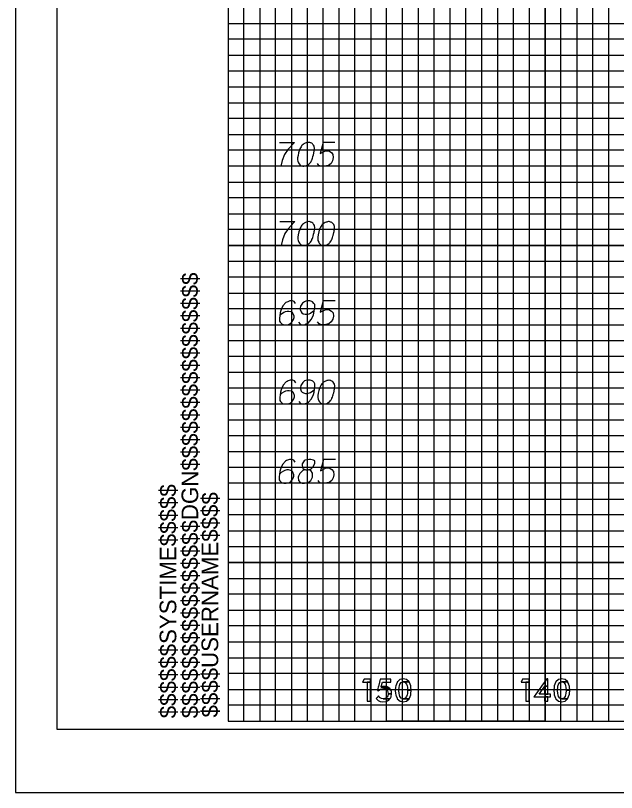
# Model space of a CAD drawing. Extents: x -13 to 323, y -5 to 1431.
# Drawn here: x -13.4 to 24.5, y -4.5 to 44.5 of the extents above; entities that cross this region are included whole.
import ezdxf

# ---------------------------------------------------------------- set-up
doc = ezdxf.new("R2010")
doc.units = 0
for name, color, linetype in [('Prop XS Elevation Labels', 7, 'Continuous'), ('Prop XS Offset Labels', 7, 'Continuous'), ('Scratch_Level_3', 7, 'Continuous'), ('Sheet Cross Section CELL', 7, 'Continuous'), ('Sheet Cross Section Grid Major CELL', 7, 'Continuous'), ('Sheet Cross Section Grid Middle CELL', 7, 'Continuous'), ('Sheet Cross Section Grid Minor 1 CELL', 7, 'Continuous'), ('Sheet Cross Section Grid Minor 2 CELL', 7, 'Continuous'), ('Sheet Cutting Line CELL', 7, 'Continuous'), ('Sheet DOT Grid CELL', 7, 'Continuous'), ('Sheet Plot Border Inside CELL', 7, 'Continuous'), ('Sheet Plot Border Outside CELL', 7, 'Continuous')]:
    doc.layers.add(name, color=color, linetype=linetype)

msp = doc.modelspace()

# ---------------------------------------------------------------- linework, layer by layer
at = {"layer": 'Prop XS Elevation Labels'}
for points in [[(3.258, 36.5), (4.203, 36.5), (4.144, 36.441), (3.801, 36.075), (3.565, 35.744), (3.423, 35.354), (3.329, 35)], [(5.1, 36.5), (5.077, 36.5), (5.006, 36.488), (4.959, 36.476), (4.923, 36.465), (4.864, 36.441), (4.793, 36.406), (4.734, 36.37), (4.675, 36.323), (4.64, 36.276), (4.604, 36.217), (4.569, 36.158), (4.534, 36.087), (4.51, 36.039), (4.486, 35.969), (4.451, 35.85), (4.415, 35.673), (4.392, 35.531), (4.392, 35.402), (4.404, 35.307), (4.451, 35.201), (4.486, 35.142), (4.545, 35.071), (4.616, 35.024), (4.652, 35.012), (4.723, 35), (4.781, 35), (4.876, 35.012), (4.959, 35.035), (5.018, 35.071), (5.1, 35.13), (5.136, 35.165), (5.183, 35.213), (5.219, 35.26), (5.242, 35.295), (5.266, 35.354), (5.278, 35.378), (5.301, 35.437), (5.325, 35.508), (5.349, 35.579), (5.36, 35.626), (5.372, 35.661), (5.384, 35.709), (5.408, 35.815), (5.419, 35.874), (5.431, 35.933), (5.443, 36.016), (5.455, 36.122), (5.455, 36.158), (5.443, 36.205), (5.431, 36.252), (5.396, 36.323), (5.36, 36.37), (5.325, 36.406), (5.278, 36.441), (5.23, 36.465), (5.195, 36.476), (5.16, 36.488), (5.1, 36.5)], [(6.742, 36.5), (5.998, 36.5), (5.809, 35.791), (6.152, 35.969), (6.352, 35.969), (6.518, 35.862), (6.612, 35.744), (6.636, 35.543), (6.6, 35.342), (6.506, 35.177), (6.341, 35.047), (6.057, 35), (5.845, 35), (5.738, 35.047), (5.644, 35.177)], [(3.276, 31.5), (4.22, 31.5), (4.161, 31.441), (3.819, 31.075), (3.583, 30.744), (3.441, 30.354), (3.346, 30)], [(5.118, 31.5), (5.094, 31.5), (5.024, 31.488), (4.977, 31.476), (4.941, 31.465), (4.882, 31.441), (4.811, 31.406), (4.752, 31.37), (4.693, 31.323), (4.658, 31.276), (4.622, 31.217), (4.587, 31.158), (4.551, 31.087), (4.528, 31.039), (4.504, 30.969), (4.469, 30.85), (4.433, 30.673), (4.409, 30.531), (4.409, 30.402), (4.421, 30.307), (4.469, 30.201), (4.504, 30.142), (4.563, 30.071), (4.634, 30.024), (4.669, 30.012), (4.74, 30), (4.799, 30), (4.894, 30.012), (4.977, 30.035), (5.036, 30.071), (5.118, 30.13), (5.154, 30.165), (5.201, 30.213), (5.236, 30.26), (5.26, 30.295), (5.283, 30.354), (5.295, 30.378), (5.319, 30.437), (5.342, 30.508), (5.366, 30.579), (5.378, 30.626), (5.39, 30.661), (5.402, 30.709), (5.425, 30.815), (5.437, 30.874), (5.449, 30.933), (5.461, 31.016), (5.473, 31.122), (5.473, 31.158), (5.461, 31.205), (5.449, 31.252), (5.413, 31.323), (5.378, 31.37), (5.342, 31.406), (5.295, 31.441), (5.248, 31.465), (5.213, 31.476), (5.177, 31.488), (5.118, 31.5)], [(6.37, 31.5), (6.346, 31.5), (6.276, 31.488), (6.228, 31.476), (6.193, 31.465), (6.134, 31.441), (6.063, 31.406), (6.004, 31.37), (5.945, 31.323), (5.909, 31.276), (5.874, 31.217), (5.838, 31.158), (5.803, 31.087), (5.779, 31.039), (5.756, 30.969), (5.721, 30.85), (5.685, 30.673), (5.661, 30.531), (5.661, 30.402), (5.673, 30.307), (5.721, 30.201), (5.756, 30.142), (5.815, 30.071), (5.886, 30.024), (5.921, 30.012), (5.992, 30), (6.051, 30), (6.146, 30.012), (6.228, 30.035), (6.287, 30.071), (6.37, 30.13), (6.406, 30.165), (6.453, 30.213), (6.488, 30.26), (6.512, 30.295), (6.535, 30.354), (6.547, 30.378), (6.571, 30.437), (6.594, 30.508), (6.618, 30.579), (6.63, 30.626), (6.642, 30.661), (6.653, 30.709), (6.677, 30.815), (6.689, 30.874), (6.701, 30.933), (6.713, 31.016), (6.724, 31.122), (6.724, 31.158), (6.713, 31.205), (6.701, 31.252), (6.665, 31.323), (6.63, 31.37), (6.594, 31.406), (6.547, 31.441), (6.5, 31.465), (6.464, 31.476), (6.429, 31.488), (6.37, 31.5)], [(4.262, 26.335), (4.168, 26.465), (4.061, 26.5), (3.896, 26.5), (3.778, 26.453), (3.707, 26.429), (3.648, 26.394), (3.459, 26.181), (3.329, 25.898), (3.294, 25.744), (3.246, 25.402), (3.246, 25.224), (3.294, 25.154), (3.388, 25.059), (3.423, 25.035), (3.542, 25), (3.695, 25), (3.813, 25.024), (3.896, 25.047), (4.014, 25.142), (4.132, 25.331), (4.168, 25.449), (4.168, 25.543), (4.109, 25.697), (4.061, 25.756), (3.979, 25.803), (3.837, 25.839), (3.73, 25.839), (3.601, 25.803), (3.518, 25.768), (3.376, 25.673), (3.305, 25.614), (3.27, 25.579)], [(4.451, 25.165), (4.545, 25.035), (4.652, 25), (4.817, 25), (4.935, 25.047), (5.006, 25.071), (5.065, 25.106), (5.254, 25.319), (5.384, 25.602), (5.419, 25.756), (5.467, 26.098), (5.467, 26.276), (5.419, 26.346), (5.325, 26.441), (5.289, 26.465), (5.171, 26.5), (5.018, 26.5), (4.9, 26.476), (4.817, 26.453), (4.699, 26.358), (4.581, 26.169), (4.545, 26.051), (4.545, 25.957), (4.604, 25.803), (4.652, 25.744), (4.734, 25.697), (4.876, 25.661), (4.982, 25.661), (5.112, 25.697), (5.195, 25.732), (5.337, 25.827), (5.408, 25.886), (5.443, 25.921)], [(6.754, 26.5), (6.01, 26.5), (5.821, 25.791), (6.163, 25.969), (6.364, 25.969), (6.529, 25.862), (6.624, 25.744), (6.647, 25.543), (6.612, 25.342), (6.517, 25.177), (6.352, 25.047), (6.069, 25), (5.856, 25), (5.75, 25.047), (5.655, 25.177)], [(4.28, 21.335), (4.185, 21.465), (4.079, 21.5), (3.914, 21.5), (3.795, 21.453), (3.725, 21.429), (3.666, 21.394), (3.477, 21.181), (3.347, 20.898), (3.311, 20.744), (3.264, 20.402), (3.264, 20.224), (3.311, 20.154), (3.406, 20.059), (3.441, 20.035), (3.559, 20), (3.713, 20), (3.831, 20.024), (3.914, 20.047), (4.032, 20.142), (4.15, 20.331), (4.185, 20.449), (4.185, 20.543), (4.126, 20.697), (4.079, 20.756), (3.996, 20.803), (3.854, 20.839), (3.748, 20.839), (3.618, 20.803), (3.536, 20.768), (3.394, 20.673), (3.323, 20.614), (3.288, 20.579)], [(4.468, 20.165), (4.563, 20.035), (4.669, 20), (4.835, 20), (4.953, 20.047), (5.024, 20.071), (5.083, 20.106), (5.272, 20.319), (5.401, 20.602), (5.437, 20.756), (5.484, 21.098), (5.484, 21.276), (5.437, 21.346), (5.342, 21.441), (5.307, 21.465), (5.189, 21.5), (5.036, 21.5), (4.917, 21.476), (4.835, 21.453), (4.717, 21.358), (4.598, 21.169), (4.563, 21.051), (4.563, 20.957), (4.622, 20.803), (4.669, 20.744), (4.752, 20.697), (4.894, 20.661), (5, 20.661), (5.13, 20.697), (5.213, 20.732), (5.354, 20.827), (5.425, 20.886), (5.461, 20.921)], [(6.382, 21.5), (6.358, 21.5), (6.287, 21.488), (6.24, 21.476), (6.204, 21.465), (6.145, 21.441), (6.074, 21.406), (6.015, 21.37), (5.956, 21.323), (5.921, 21.276), (5.885, 21.217), (5.85, 21.158), (5.815, 21.087), (5.791, 21.039), (5.767, 20.969), (5.732, 20.85), (5.697, 20.673), (5.673, 20.531), (5.673, 20.402), (5.685, 20.307), (5.732, 20.201), (5.767, 20.142), (5.827, 20.071), (5.897, 20.024), (5.933, 20.012), (6.004, 20), (6.063, 20), (6.157, 20.012), (6.24, 20.035), (6.299, 20.071), (6.382, 20.13), (6.417, 20.165), (6.464, 20.213), (6.5, 20.26), (6.523, 20.295), (6.547, 20.354), (6.559, 20.378), (6.582, 20.437), (6.606, 20.508), (6.63, 20.579), (6.642, 20.626), (6.653, 20.661), (6.665, 20.709), (6.689, 20.815), (6.701, 20.874), (6.712, 20.933), (6.724, 21.016), (6.736, 21.122), (6.736, 21.158), (6.724, 21.205), (6.712, 21.252), (6.677, 21.323), (6.642, 21.37), (6.606, 21.406), (6.559, 21.441), (6.512, 21.465), (6.476, 21.476), (6.441, 21.488), (6.382, 21.5)], [(4.238, 16.335), (4.144, 16.465), (4.038, 16.5), (3.872, 16.5), (3.754, 16.453), (3.683, 16.429), (3.624, 16.394), (3.435, 16.181), (3.305, 15.898), (3.27, 15.744), (3.223, 15.402), (3.223, 15.224), (3.27, 15.154), (3.364, 15.059), (3.4, 15.035), (3.518, 15), (3.671, 15), (3.79, 15.024), (3.872, 15.047), (3.99, 15.142), (4.108, 15.331), (4.144, 15.449), (4.144, 15.543), (4.085, 15.697), (4.038, 15.756), (3.955, 15.803), (3.813, 15.839), (3.707, 15.839), (3.577, 15.803), (3.494, 15.768), (3.352, 15.673), (3.282, 15.614), (3.246, 15.579)], [(4.899, 15.85), (5.065, 15.85), (5.112, 15.862), (5.254, 15.921), (5.36, 16.016), (5.478, 16.24), (5.466, 16.406), (5.384, 16.465), (5.218, 16.5), (5.1, 16.5), (4.876, 16.465), (4.805, 16.406), (4.687, 16.228), (4.675, 16.169), (4.699, 15.992), (4.746, 15.921), (4.899, 15.85), (4.711, 15.803), (4.533, 15.626), (4.439, 15.449), (4.427, 15.39), (4.439, 15.165), (4.545, 15.047), (4.687, 15), (4.829, 15), (5.053, 15.059), (5.218, 15.165), (5.325, 15.378), (5.337, 15.449), (5.325, 15.638), (5.23, 15.803), (5.065, 15.85)], [(6.777, 16.5), (6.033, 16.5), (5.844, 15.791), (6.187, 15.969), (6.388, 15.969), (6.553, 15.862), (6.648, 15.744), (6.671, 15.543), (6.636, 15.342), (6.541, 15.177), (6.376, 15.047), (6.092, 15), (5.88, 15), (5.773, 15.047), (5.679, 15.177)]]:
    msp.add_lwpolyline(points, dxfattribs=at)
at = {"layer": 'Prop XS Offset Labels'}
for points in [[(8.581, 2.641), (8.492, 2.459), (8.99, 2.459), (8.99, 2.641)], [(8.781, 2.459), (8.781, 1.25), (8.99, 1.25), (8.99, 2.459)], [(9.427, 1.94), (9.424, 1.928), (9.495, 1.928), (9.508, 1.94), (9.524, 1.954), (9.595, 1.997), (9.627, 2.007), (9.697, 2.029), (9.811, 2.035), (10.219, 2.035), (10.211, 2.05), (10.076, 2.145), (9.655, 2.145), (9.658, 2.158), (9.658, 2.158), (9.663, 2.178), (9.738, 2.456), (10.263, 2.456), (10.263, 2.641), (9.6, 2.641), (9.554, 2.456), (9.486, 2.178), (9.481, 2.158), (9.478, 2.145), (9.454, 2.05), (9.451, 2.035), (9.449, 2.029), (9.444, 2.007), (9.441, 1.997), (9.431, 1.954)], [(10.851, 1.255), (11.051, 1.214), (11.245, 1.255), (11.256, 1.257), (11.422, 1.409), (11.047, 1.409), (11.038, 1.411), (11.033, 1.413), (10.928, 1.442), (10.841, 1.555), (10.841, 1.556), (10.841, 1.556), (10.813, 1.657), (10.813, 1.659), (10.793, 1.732), (10.792, 1.736), (10.774, 1.939), (10.774, 1.941), (10.774, 1.943), (10.792, 2.145), (10.812, 2.222), (10.813, 2.224), (10.839, 2.322), (10.84, 2.325), (10.928, 2.44), (11.041, 2.469), (11.045, 2.47), (11.055, 2.473), (11.425, 2.473), (11.262, 2.622), (11.254, 2.624), (11.053, 2.668), (11.053, 2.668), (10.845, 2.624), (10.843, 2.622), (10.681, 2.473), (10.678, 2.47), (10.678, 2.469), (10.665, 2.44), (10.618, 2.325), (10.617, 2.322), (10.577, 2.224), (10.576, 2.222), (10.568, 2.145), (10.547, 1.943), (10.547, 1.941), (10.547, 1.939), (10.567, 1.736), (10.568, 1.732), (10.575, 1.659), (10.575, 1.657), (10.616, 1.556), (10.617, 1.555), (10.663, 1.442), (10.675, 1.413), (10.676, 1.411), (10.679, 1.409), (10.848, 1.257)], [(11.312, 2.145), (11.328, 1.943), (11.555, 1.943), (11.536, 2.145), (11.528, 2.222), (11.527, 2.224), (11.527, 2.224), (11.488, 2.322), (11.488, 2.322), (11.487, 2.325), (11.441, 2.44), (11.44, 2.44), (11.429, 2.469), (11.428, 2.47), (11.425, 2.473), (11.055, 2.473), (11.065, 2.47), (11.068, 2.469), (11.175, 2.44), (11.262, 2.325), (11.265, 2.322), (11.291, 2.224), (11.291, 2.222)], [(18.581, 2.641), (18.492, 2.459), (18.99, 2.459), (18.99, 2.641)], [(18.781, 2.459), (18.781, 1.25), (18.99, 1.25), (18.99, 2.459)], [(19.411, 1.693), (19.297, 1.534), (20.35, 1.534), (20.35, 1.693), (19.618, 1.693), (19.878, 2.059), (19.935, 2.139), (19.977, 2.199), (20.179, 2.199), (20.179, 2.668), (20.114, 2.668), (19.775, 2.199), (19.733, 2.139), (19.675, 2.059)], [(20.851, 1.255), (21.051, 1.214), (21.245, 1.255), (21.256, 1.257), (21.422, 1.409), (21.047, 1.409), (21.038, 1.411), (21.033, 1.413), (20.928, 1.442), (20.841, 1.555), (20.841, 1.556), (20.841, 1.556), (20.813, 1.657), (20.813, 1.659), (20.793, 1.732), (20.792, 1.736), (20.774, 1.939), (20.774, 1.941), (20.774, 1.943), (20.792, 2.145), (20.812, 2.222), (20.813, 2.224), (20.839, 2.322), (20.84, 2.325), (20.928, 2.44), (21.041, 2.469), (21.045, 2.47), (21.055, 2.473), (21.425, 2.473), (21.262, 2.622), (21.254, 2.624), (21.053, 2.668), (21.053, 2.668), (20.845, 2.624), (20.843, 2.622), (20.681, 2.473), (20.678, 2.47), (20.678, 2.469), (20.665, 2.44), (20.618, 2.325), (20.617, 2.322), (20.577, 2.224), (20.576, 2.222), (20.568, 2.145), (20.547, 1.943), (20.547, 1.941), (20.547, 1.939), (20.567, 1.736), (20.567, 1.732), (20.575, 1.659), (20.575, 1.657), (20.616, 1.556), (20.617, 1.555), (20.663, 1.442), (20.675, 1.413), (20.676, 1.411), (20.679, 1.409), (20.848, 1.257)], [(21.312, 2.145), (21.328, 1.943), (21.555, 1.943), (21.536, 2.145), (21.528, 2.222), (21.527, 2.224), (21.527, 2.224), (21.488, 2.322), (21.488, 2.322), (21.487, 2.325), (21.441, 2.44), (21.44, 2.44), (21.429, 2.469), (21.428, 2.47), (21.425, 2.473), (21.055, 2.473), (21.065, 2.47), (21.068, 2.469), (21.175, 2.44), (21.262, 2.325), (21.265, 2.322), (21.291, 2.224), (21.291, 2.222)], [(9.692, 2.158), (9.655, 2.145), (10.076, 2.145), (10.058, 2.158), (9.961, 2.178), (9.75, 2.178)], [(9.888, 2.192), (9.75, 2.178), (9.96, 2.178), (9.888, 2.192)], [(10.083, 1.841), (10.105, 1.721), (10.318, 1.721), (10.307, 1.841), (10.307, 1.841), (10.303, 1.881), (10.284, 1.916), (10.278, 1.928), (10.271, 1.94), (10.263, 1.954), (10.24, 1.997), (10.235, 2.007), (10.223, 2.029), (10.219, 2.035), (9.811, 2.035), (9.838, 2.029), (9.928, 2.007), (9.943, 1.997), (10.003, 1.954), (10.024, 1.94), (10.031, 1.928), (10.038, 1.916), (10.059, 1.881)], [(19.97, 2.059), (19.97, 1.693), (20.179, 1.693), (20.179, 2.059), (20.179, 2.139), (20.179, 2.199), (19.977, 2.199), (19.973, 2.139)], [(9.626, 1.233), (9.762, 1.214), (9.959, 1.233), (9.968, 1.237), (10.091, 1.297), (10.091, 1.297), (10.141, 1.321), (10.185, 1.375), (10.204, 1.399), (9.793, 1.399), (9.683, 1.418), (9.682, 1.419), (9.679, 1.42), (9.596, 1.466), (9.586, 1.477), (9.58, 1.483), (9.58, 1.483), (9.529, 1.535), (9.497, 1.585), (9.497, 1.585), (9.451, 1.535), (9.404, 1.483), (9.399, 1.477), (9.39, 1.466), (9.348, 1.42), (9.347, 1.419), (9.348, 1.418), (9.363, 1.399), (9.382, 1.375), (9.445, 1.321), (9.474, 1.297), (9.598, 1.237)], [(9.424, 1.928), (9.482, 1.916), (9.495, 1.928)], [(9.9, 1.418), (9.793, 1.399), (10.204, 1.399), (10.22, 1.418), (10.221, 1.419), (10.222, 1.42), (10.222, 1.42), (10.259, 1.466), (10.268, 1.477), (10.27, 1.483), (10.284, 1.535), (10.299, 1.59), (10.322, 1.674), (10.318, 1.721), (10.105, 1.721), (10.097, 1.674), (10.082, 1.59), (10.047, 1.535), (10.014, 1.483), (10.004, 1.477), (9.987, 1.466), (9.913, 1.42), (9.905, 1.419)], [(11.058, 1.411), (11.047, 1.409), (11.422, 1.409), (11.425, 1.411), (11.426, 1.413), (11.438, 1.442), (11.485, 1.555), (11.485, 1.556), (11.527, 1.657), (11.528, 1.659), (11.535, 1.732), (11.535, 1.736), (11.555, 1.939), (11.556, 1.941), (11.555, 1.943), (11.328, 1.943), (11.328, 1.941), (11.328, 1.939), (11.312, 1.736), (11.312, 1.732), (11.292, 1.659), (11.291, 1.657), (11.264, 1.556), (11.263, 1.555), (11.175, 1.442), (11.063, 1.413)], [(19.97, 1.534), (19.97, 1.25), (20.179, 1.25), (20.179, 1.534)], [(21.058, 1.411), (21.047, 1.409), (21.422, 1.409), (21.425, 1.411), (21.426, 1.413), (21.438, 1.442), (21.485, 1.555), (21.485, 1.556), (21.527, 1.657), (21.528, 1.659), (21.535, 1.732), (21.535, 1.736), (21.555, 1.939), (21.556, 1.941), (21.555, 1.943), (21.328, 1.943), (21.328, 1.941), (21.328, 1.939), (21.312, 1.736), (21.312, 1.732), (21.292, 1.659), (21.291, 1.657), (21.264, 1.556), (21.263, 1.555), (21.175, 1.442), (21.063, 1.413)]]:
    msp.add_lwpolyline(points, close=True, dxfattribs=at)
at = {"layer": 'Scratch_Level_3'}
msp.add_lwpolyline([(20, 40), (300, 40), (300, 10), (20, 10)], close=True, dxfattribs=at)
at = {"layer": 'Sheet Cross Section CELL'}
msp.add_line((0, 0), (0, 0), dxfattribs=at)
msp.add_line((0, 0), (0, 0), dxfattribs=at)
msp.add_line((0, 0), (0, 0), dxfattribs=at)
msp.add_line((0, 0), (0, 0), dxfattribs=at)
msp.add_line((0, 0), (0, 0), dxfattribs=at)
msp.add_line((0, 0), (0, 0), dxfattribs=at)
msp.add_line((0, 0), (0, 0), dxfattribs=at)
msp.add_lwpolyline([(320, 210), (0, 210), (0, 0), (320, 0)], close=True, dxfattribs=at)
at = {"layer": 'Sheet Cross Section Grid Major CELL'}
for p, q in [((10, 0), (10, 210)), ((20, 210), (20, 0)), ((20, 0), (10, 0))]:
    msp.add_line(p, q, dxfattribs=at)
for points in [[(0, 40), (320, 40), (320, 30), (0, 30)], [(0, 20), (320, 20), (320, 10), (0, 10)]]:
    msp.add_lwpolyline(points, dxfattribs=at)
at = {"layer": 'Sheet Cross Section Grid Middle CELL'}
for points in [[(5, 210), (5, 0), (15, 0), (15, 210)], [(0, 25), (320, 25), (320, 35), (0, 35)], [(0, 5), (320, 5), (320, 15), (0, 15)]]:
    msp.add_lwpolyline(points, dxfattribs=at)
at = {"layer": 'Sheet Cross Section Grid Minor 1 CELL'}
for points in [[(0, 44), (320, 44), (320, 43), (0, 43)], [(0, 42), (320, 42), (320, 41), (0, 41)], [(0, 39), (320, 39), (320, 38), (0, 38)], [(0, 37), (320, 37), (320, 36), (0, 36)], [(0, 34), (320, 34), (320, 33), (0, 33)], [(0, 32), (320, 32), (320, 31), (0, 31)], [(0, 29), (320, 29), (320, 28), (0, 28)], [(0, 27), (320, 27), (320, 26), (0, 26)], [(0, 24), (320, 24), (320, 23), (0, 23)], [(0, 22), (320, 22), (320, 21), (0, 21)], [(0, 19), (320, 19), (320, 18), (0, 18)], [(0, 17), (320, 17), (320, 16), (0, 16)], [(0, 14), (320, 14), (320, 13), (0, 13)], [(0, 12), (320, 12), (320, 11), (0, 11)], [(0, 9), (320, 9), (320, 8), (0, 8)], [(0, 7), (320, 7), (320, 6), (0, 6)], [(0, 4), (320, 4), (320, 3), (0, 3)], [(0, 2), (320, 2), (320, 1), (0, 1)]]:
    msp.add_lwpolyline(points, dxfattribs=at)
at = {"layer": 'Sheet Cross Section Grid Minor 2 CELL'}
for points in [[(0, 0), (1, 0), (1, 210), (2, 210), (2, 0)], [(2, 0), (3, 0), (3, 210), (4, 210), (4, 0)], [(5, 0), (6, 0), (6, 210), (7, 210), (7, 0)], [(7, 0), (8, 0), (8, 210), (9, 210), (9, 0)], [(10, 0), (11, 0), (11, 210), (12, 210), (12, 0)], [(12, 0), (13, 0), (13, 210), (14, 210), (14, 0)], [(15, 0), (16, 0), (16, 210), (17, 210), (17, 0)], [(17, 0), (18, 0), (18, 210), (19, 210), (19, 0)], [(20, 0), (21, 0), (21, 210), (22, 210), (22, 0)], [(22, 0), (23, 0), (23, 210), (24, 210), (24, 0)]]:
    msp.add_lwpolyline(points, dxfattribs=at)
at = {"layer": 'Sheet Cutting Line CELL'}
for p, q in [((-13.4, 214.5), (-13.4, -4.5)), ((-13.4, -4.5), (323.3, -4.5))]:
    msp.add_line(p, q, dxfattribs=at)
at = {"layer": 'Sheet DOT Grid CELL'}
for p, q in [((10, 0), (10, 210)), ((20, 0), (20, 210)), ((0, 40), (320, 40)), ((0, 30), (320, 30)), ((0, 20), (320, 20)), ((0, 10), (320, 10))]:
    msp.add_line(p, q, dxfattribs=at)
at = {"layer": 'Sheet Plot Border Inside CELL'}
msp.add_lwpolyline([(-10.8, -0.5), (322.4, -0.5), (322.4, 210.5), (-10.8, 210.5)], close=True, dxfattribs=at)
at = {"layer": 'Sheet Plot Border Outside CELL'}
msp.add_lwpolyline([(-13.4, -4.5), (323.3, -4.5), (323.3, 214.5), (-13.4, 214.5)], close=True, dxfattribs=at)

# ---------------------------------------------------------------- texts
at = {"layer": 'Sheet Cross Section CELL'}
for s, p in [('$$$$$$$$$$$$$$$$DGN$$$$$$$$$$$$$$$$', (-1.88, 0.18)), ('$$$$$$SYSTIME$$$$$', (-3.26, 0.18)), ('$$$$USERNAME$$$$', (-0.62, 0.23))]:
    msp.add_text(s, height=1.05, rotation=90, dxfattribs=at).set_placement(p)

doc.saveas('drawing.dxf')
